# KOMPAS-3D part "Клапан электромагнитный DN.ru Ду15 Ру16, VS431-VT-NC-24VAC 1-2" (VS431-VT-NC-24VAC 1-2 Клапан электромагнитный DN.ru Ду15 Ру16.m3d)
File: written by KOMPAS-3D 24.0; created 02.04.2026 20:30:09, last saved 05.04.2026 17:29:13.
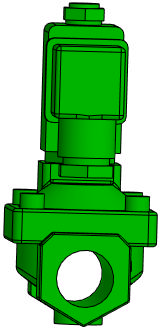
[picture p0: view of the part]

Document properties: Автор: artio; Полное имя файла: C:\Users\artio\OneDrive\Рабочий стол\Клапан электромагнитный DN.ru\VS431\VS431-VT-NC\VS431-VT-NC-24VAC\Ду15\VS431-VT-NC-24VAC 1-2 Клапан электромагнитный DN.ru Ду15 Ру16.m3d

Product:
- Body: Тело 1  | qty 1
    Масса: 1.030062
- Part/product: Клапан электромагнитный DN.ru Ду15 Ру16  | designation VS431-VT-NC-24VAC 1-2
    Масса: 0.732
    Раздел спецификации: Прочие изделия
    Примечание: D130-05639
    additional columns: ef56311e-7521-43dc-8291-0e6108b3d81d; VS400-ET-NC-220VAC 1-2; artio; c; Шероховатость не задана; Да

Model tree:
1. Операция без истории:1

Expressions: VS431-VT-NC-24VAC 1-2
